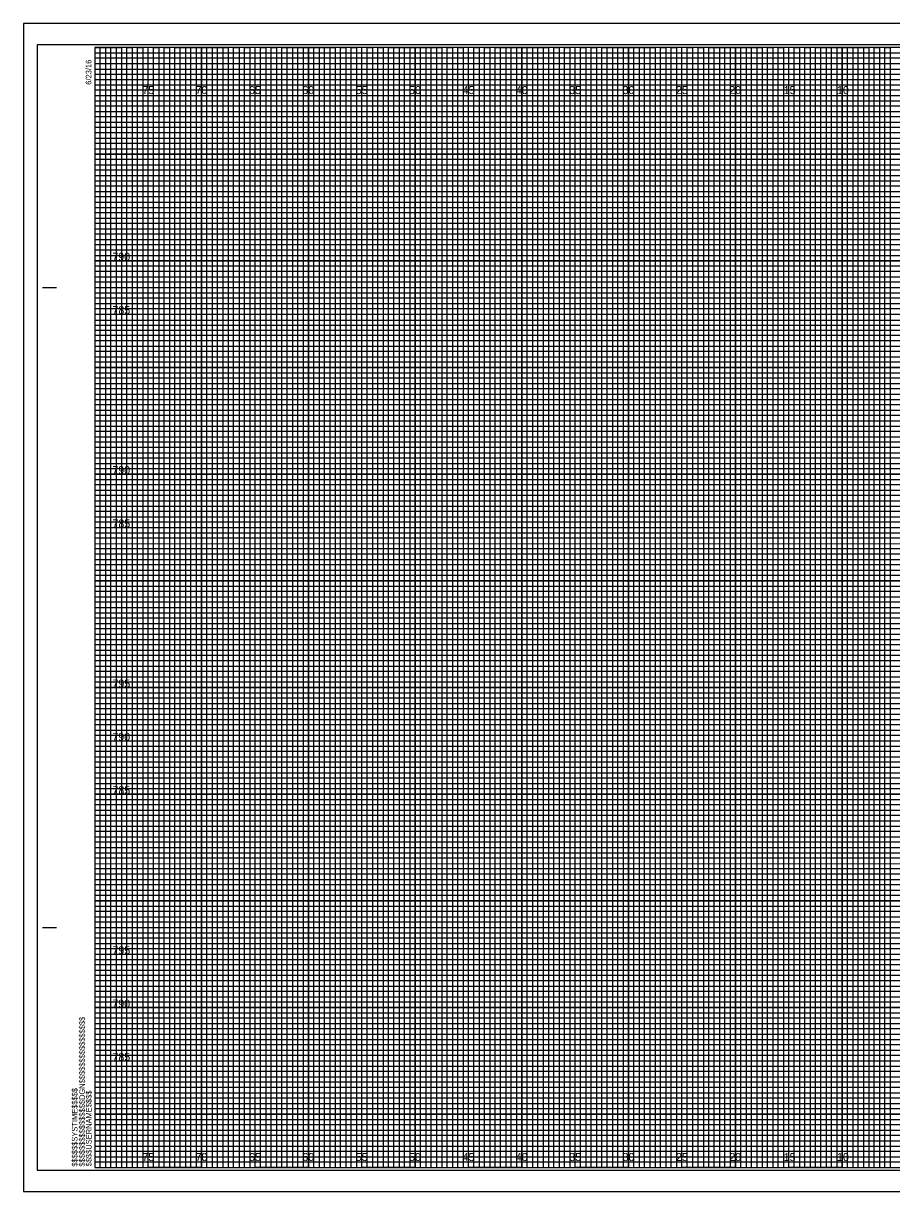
# Model space of a CAD drawing. Extents: x -7 to 162, y 108 to 217.
# Drawn here: x -6.7 to 74.6, y 107.7 to 217.2 of the extents above; entities that cross this region are included whole.
import ezdxf

# ---------------------------------------------------------------- set-up
doc = ezdxf.new("R2010")
doc.units = 0
for name, color, linetype in [('Exist Cross Section Cell', 7, 'Continuous'), ('Exist XS Center Line Elevation Label', 7, 'Continuous'), ('Prop CMT Pvmt Course 2 Wedge', 7, 'Continuous'), ('Prop XS Hydro Elevations', 7, 'Continuous'), ('Prop XS Retaining Wall', 7, 'Continuous'), ('Prop XS SE Text', 7, 'Continuous'), ('Prop XS Side Slope Text', 7, 'Continuous'), ('Sheet Cutting Line CELL', 7, 'Continuous'), ('Sheet DOT Grid CELL', 7, 'Continuous'), ('Sheet Plot Border Inside CELL', 7, 'Continuous'), ('Sheet Plot Border Outside CELL', 7, 'Continuous')]:
    doc.layers.add(name, color=color, linetype=linetype)

msp = doc.modelspace()

# ---------------------------------------------------------------- linework, layer by layer
at = {"layer": 'Exist Cross Section Cell'}
for p, q in [((5, 215), (0, 215)), ((5, 110), (5, 215)), ((15, 215), (10, 215)), ((10, 215), (10, 110)), ((15, 110), (15, 215)), ((25, 215), (20, 215)), ((20, 215), (20, 110)), ((25, 110), (25, 215)), ((35, 215), (30, 215)), ((30, 215), (30, 110)), ((35, 110), (35, 215)), ((45, 215), (40, 215)), ((40, 215), (40, 110)), ((45, 110), (45, 215)), ((55, 215), (50, 215)), ((50, 215), (50, 110)), ((55, 110), (55, 215)), ((65, 215), (60, 215)), ((60, 215), (60, 110)), ((65, 110), (65, 215)), ((75, 215), (70, 215)), ((70, 215), (70, 110)), ((10, 110), (5, 110)), ((20, 110), (15, 110)), ((30, 110), (25, 110)), ((40, 110), (35, 110)), ((50, 110), (45, 110)), ((60, 110), (55, 110)), ((70, 110), (65, 110))]:
    msp.add_line(p, q, dxfattribs=at)
for points in [[(0, 210), (160, 210), (160, 205), (0, 205)], [(0, 200), (160, 200), (160, 195), (0, 195)], [(0, 190), (160, 190), (160, 185), (0, 185)], [(0, 180), (160, 180), (160, 175), (0, 175)], [(0, 170), (160, 170), (160, 165), (0, 165)], [(0, 160), (160, 160), (160, 155), (0, 155)], [(0, 150), (160, 150), (160, 145), (0, 145)], [(0, 140), (160, 140), (160, 135), (0, 135)], [(0, 130), (160, 130), (160, 125), (0, 125)], [(0, 120), (160, 120), (160, 115), (0, 115)]]:
    msp.add_lwpolyline(points, dxfattribs=at)
at = {"layer": 'Exist XS Center Line Elevation Label'}
for points in [[(0, 215), (2.5, 215), (2.5, 110), (7.5, 110), (7.5, 215), (12.5, 215), (12.5, 110), (17.5, 110), (17.5, 215), (22.5, 215), (22.5, 110), (27.5, 110), (27.5, 215), (32.5, 215), (32.5, 110), (37.5, 110), (37.5, 215), (42.5, 215), (42.5, 110), (47.5, 110), (47.5, 215), (52.5, 215), (52.5, 110), (57.5, 110), (57.5, 215), (62.5, 215), (62.5, 110), (67.5, 110), (67.5, 215), (72.5, 215), (72.5, 110), (77.5, 110)], [(0, 212.5), (137.5, 212.5)], [(0, 202.5), (160, 202.5), (160, 207.5), (0, 207.5)], [(0, 192.5), (160, 192.5), (160, 197.5), (0, 197.5)], [(0, 182.5), (160, 182.5), (160, 187.5), (0, 187.5)], [(0, 172.5), (160, 172.5), (160, 177.5), (0, 177.5)], [(0, 162.5), (160, 162.5), (160, 167.5), (0, 167.5)], [(0, 152.5), (160, 152.5), (160, 157.5), (0, 157.5)], [(0, 142.5), (160, 142.5), (160, 147.5), (0, 147.5)], [(0, 132.5), (160, 132.5), (160, 137.5), (0, 137.5)], [(0, 122.5), (160, 122.5), (160, 127.5), (0, 127.5)], [(0, 112.5), (160, 112.5), (160, 117.5), (0, 117.5)]]:
    msp.add_lwpolyline(points, dxfattribs=at)
at = {"layer": 'Prop XS Hydro Elevations'}
for p, q in [((-4.9, 192.5), (-3.65, 192.5)), ((-4.85, 192.5), (-3.6, 192.5)), ((-4.9, 132.5), (-3.65, 132.5)), ((-4.85, 132.5), (-3.6, 132.5)), ((0, 110), (0, 110)), ((0, 110), (0, 110)), ((0, 110), (0, 110)), ((0, 110), (0, 110)), ((0, 110), (0, 110)), ((0, 110), (0, 110)), ((0, 110), (0, 110))]:
    msp.add_line(p, q, dxfattribs=at)
msp.add_lwpolyline([(160, 215), (0, 215), (0, 110), (160, 110)], close=True, dxfattribs=at)
at = {"layer": 'Prop XS Retaining Wall'}
for points in [[(0, 110), (0.5, 110), (0.5, 215), (1, 215), (1, 110)], [(1, 110), (1.5, 110), (1.5, 215), (2, 215), (2, 110)], [(2.5, 110), (3, 110), (3, 215), (3.5, 215), (3.5, 110)], [(3.5, 110), (4, 110), (4, 215), (4.5, 215), (4.5, 110)], [(5, 110), (5.5, 110), (5.5, 215), (6, 215), (6, 110)], [(6, 110), (6.5, 110), (6.5, 215), (7, 215), (7, 110)], [(7.5, 110), (8, 110), (8, 215), (8.5, 215), (8.5, 110)], [(8.5, 110), (9, 110), (9, 215), (9.5, 215), (9.5, 110)], [(10, 110), (10.5, 110), (10.5, 215), (11, 215), (11, 110)], [(11, 110), (11.5, 110), (11.5, 215), (12, 215), (12, 110)], [(12.5, 110), (13, 110), (13, 215), (13.5, 215), (13.5, 110)], [(13.5, 110), (14, 110), (14, 215), (14.5, 215), (14.5, 110)], [(15, 110), (15.5, 110), (15.5, 215), (16, 215), (16, 110)], [(16, 110), (16.5, 110), (16.5, 215), (17, 215), (17, 110)], [(17.5, 110), (18, 110), (18, 215), (18.5, 215), (18.5, 110)], [(18.5, 110), (19, 110), (19, 215), (19.5, 215), (19.5, 110)], [(20, 110), (20.5, 110), (20.5, 215), (21, 215), (21, 110)], [(21, 110), (21.5, 110), (21.5, 215), (22, 215), (22, 110)], [(22.5, 110), (23, 110), (23, 215), (23.5, 215), (23.5, 110)], [(23.5, 110), (24, 110), (24, 215), (24.5, 215), (24.5, 110)], [(25, 110), (25.5, 110), (25.5, 215), (26, 215), (26, 110)], [(26, 110), (26.5, 110), (26.5, 215), (27, 215), (27, 110)], [(27.5, 110), (28, 110), (28, 215), (28.5, 215), (28.5, 110)], [(28.5, 110), (29, 110), (29, 215), (29.5, 215), (29.5, 110)], [(30, 110), (30.5, 110), (30.5, 215), (31, 215), (31, 110)], [(31, 110), (31.5, 110), (31.5, 215), (32, 215), (32, 110)], [(32.5, 110), (33, 110), (33, 215), (33.5, 215), (33.5, 110)], [(33.5, 110), (34, 110), (34, 215), (34.5, 215), (34.5, 110)], [(35, 110), (35.5, 110), (35.5, 215), (36, 215), (36, 110)], [(36, 110), (36.5, 110), (36.5, 215), (37, 215), (37, 110)], [(37.5, 110), (38, 110), (38, 215), (38.5, 215), (38.5, 110)], [(38.5, 110), (39, 110), (39, 215), (39.5, 215), (39.5, 110)], [(40, 110), (40.5, 110), (40.5, 215), (41, 215), (41, 110)], [(41, 110), (41.5, 110), (41.5, 215), (42, 215), (42, 110)], [(42.5, 110), (43, 110), (43, 215), (43.5, 215), (43.5, 110)], [(43.5, 110), (44, 110), (44, 215), (44.5, 215), (44.5, 110)], [(45, 110), (45.5, 110), (45.5, 215), (46, 215), (46, 110)], [(46, 110), (46.5, 110), (46.5, 215), (47, 215), (47, 110)], [(47.5, 110), (48, 110), (48, 215), (48.5, 215), (48.5, 110)], [(48.5, 110), (49, 110), (49, 215), (49.5, 215), (49.5, 110)], [(50, 110), (50.5, 110), (50.5, 215), (51, 215), (51, 110)], [(51, 110), (51.5, 110), (51.5, 215), (52, 215), (52, 110)], [(52.5, 110), (53, 110), (53, 215), (53.5, 215), (53.5, 110)], [(53.5, 110), (54, 110), (54, 215), (54.5, 215), (54.5, 110)], [(55, 110), (55.5, 110), (55.5, 215), (56, 215), (56, 110)], [(56, 110), (56.5, 110), (56.5, 215), (57, 215), (57, 110)], [(57.5, 110), (58, 110), (58, 215), (58.5, 215), (58.5, 110)], [(58.5, 110), (59, 110), (59, 215), (59.5, 215), (59.5, 110)], [(60, 110), (60.5, 110), (60.5, 215), (61, 215), (61, 110)], [(61, 110), (61.5, 110), (61.5, 215), (62, 215), (62, 110)], [(62.5, 110), (63, 110), (63, 215), (63.5, 215), (63.5, 110)], [(63.5, 110), (64, 110), (64, 215), (64.5, 215), (64.5, 110)], [(65, 110), (65.5, 110), (65.5, 215), (66, 215), (66, 110)], [(66, 110), (66.5, 110), (66.5, 215), (67, 215), (67, 110)], [(67.5, 110), (68, 110), (68, 215), (68.5, 215), (68.5, 110)], [(68.5, 110), (69, 110), (69, 215), (69.5, 215), (69.5, 110)], [(70, 110), (70.5, 110), (70.5, 215), (71, 215), (71, 110)], [(71, 110), (71.5, 110), (71.5, 215), (72, 215), (72, 110)], [(72.5, 110), (73, 110), (73, 215), (73.5, 215), (73.5, 110)], [(73.5, 110), (74, 110), (74, 215), (74.5, 215), (74.5, 110)]]:
    msp.add_lwpolyline(points, dxfattribs=at)
at = {"layer": 'Prop XS Side Slope Text'}
for p, q in [((0, 214.5), (130, 214.5)), ((130, 213.99), (0, 213.99)), ((0, 213.99), (0, 213.5)), ((0, 213.5), (130, 213.5)), ((130, 212.94), (0, 212.94)), ((0, 212.94), (0, 212)), ((0, 212), (160, 212))]:
    msp.add_line(p, q, dxfattribs=at)
for points in [[(0, 211.5), (135, 211.5), (160, 211.5), (160, 211), (0, 211)], [(0, 210.5), (160, 210.5), (160, 209.5), (0, 209.5)], [(0, 209), (160, 209), (160, 208.5), (0, 208.49)], [(0, 208), (160, 208), (160, 207), (0, 207)], [(0, 206.5), (160, 206.5), (160, 206), (0, 206)], [(0, 205.5), (160, 205.5), (160, 204.5), (0, 204.5)], [(0, 204), (160, 204), (160, 203.5), (0, 203.5)], [(0, 203), (160, 203), (160, 202), (0, 202)], [(0, 201.5), (160, 201.5), (160, 201), (0, 201)], [(0, 200.5), (160, 200.5), (160, 199.5), (0, 199.5)], [(0, 199), (160, 199), (160, 198.5), (0, 198.5)], [(0, 198), (160, 198), (160, 196.97), (160, 196.5), (160, 196), (0, 196)], [(0, 197), (160, 197), (160, 196.5), (0, 196.5)], [(0, 195.5), (160, 195.5), (160, 194.5), (0, 194.52)], [(0, 194.52), (160, 194.5), (160, 194), (0, 194)], [(0, 193.5), (160, 193.5), (160, 193), (0, 193)], [(0, 192), (160, 192), (160, 191.5), (0, 191.5)], [(0, 191), (160, 191), (160, 190.5), (0, 190.5)], [(-0.04, 189.44), (160, 189.44), (160, 188.94), (-0.04, 188.94)], [(0, 188.5), (160, 188.5), (160, 188), (0, 188)], [(0, 187), (160, 187), (160, 186.5), (0, 186.5)], [(0, 186), (160, 186), (160, 185.5), (0, 185.5)], [(0, 184.5), (160, 184.5), (160, 184), (0, 184)], [(0, 183.5), (160, 183.5), (160, 183), (0, 183)], [(0, 182), (160, 182), (160, 181.5), (0, 181.5)], [(0, 181), (160, 181), (160, 180.5), (0, 180.5)], [(0, 179.5), (160, 179.5), (160, 178.99), (0, 179)], [(0, 178.5), (160, 178.5), (160, 178), (0, 178)], [(0, 177), (160, 177), (160, 176.5), (0, 176.5)], [(0, 176), (160, 176), (160, 175.5), (0, 175.5)], [(0, 174.5), (160, 174.5), (160, 174), (0, 174)], [(0, 173.5), (160, 173.5), (160, 173), (0, 173)], [(0, 172), (160, 172), (160, 171.5), (0, 171.5)], [(0, 171), (160, 171), (160, 170.5), (0, 170.5)], [(0, 169.5), (160, 169.5), (160, 169), (0, 169)], [(0, 168.5), (160.03, 168.46), (160, 168), (0, 168)], [(0, 167), (160, 167), (160, 166.5), (0, 166.5)], [(0, 166), (160, 166), (160, 165.5), (0, 165.5)], [(0, 164.5), (160, 164.5), (160, 164), (0, 164)], [(0, 163.5), (160, 163.5), (160, 163), (0, 163)], [(0, 162), (160, 162), (160, 161.5), (0, 161.5)], [(0, 161), (160, 161), (160, 160.5), (0, 160.5)], [(0, 159.5), (160, 159.5), (160, 159), (0, 159)], [(0, 158.5), (160, 158.5), (160, 158), (0, 158)], [(0, 157), (160, 157), (160, 156.5), (0, 156.5)], [(0, 156), (160, 156), (160, 155.5), (0, 155.5)], [(0, 154.5), (160, 154.5), (160, 154), (0, 154)], [(0, 153.5), (160, 153.5), (160, 153), (0, 153)], [(0, 152), (160, 152), (160, 151.5), (0, 151.5)], [(0, 151), (160, 151), (160, 150.5), (0, 150.5)], [(0, 149.5), (160, 149.5), (160, 148.99), (0, 149)], [(0, 148.5), (160, 148.5), (160, 148), (0, 148)], [(0, 147), (160, 147), (160, 146.5), (0, 146.5)], [(0, 146), (160, 146), (160, 145.5), (0, 145.5)], [(0, 144.5), (160, 144.5), (160, 144), (0, 144)], [(0, 143.5), (160, 143.5), (160, 143), (0, 143)], [(0, 142), (160, 142), (160, 141.5), (0, 141.5)], [(0, 141), (160, 141), (160, 140.5), (0, 140.5)], [(0, 139.5), (160, 139.5), (160, 139), (0, 139)], [(0, 138.5), (160.03, 138.46), (160, 138), (0, 138)], [(0, 137), (160, 137), (160, 136.5), (0, 136.5)], [(0, 136), (160, 136), (160, 135.5), (0, 135.5)], [(0, 134.5), (160, 134.5), (160, 134), (0, 134)], [(0, 133.5), (160, 133.5), (160, 133), (0, 133)], [(0, 132), (160, 132), (160, 131.5), (0, 131.5)], [(0, 131), (160, 131), (160, 130.5), (0, 130.5)], [(0, 129.5), (160, 129.5), (160, 129), (0, 129)], [(0, 128.5), (160, 128.5), (160, 128), (0, 128)], [(0, 127), (160, 127), (160, 126.5), (0, 126.5)], [(0, 126), (160, 126), (160, 125.5), (0, 125.5)], [(0, 124.5), (160, 124.5), (160, 124), (0, 124)], [(0, 123.5), (160, 123.5), (160, 123), (0, 123)], [(0, 122), (160, 122), (160, 121.5), (0, 121.5)], [(0, 121), (160, 121), (160, 120.5), (0, 120.5)], [(0, 119.5), (160, 119.5), (160, 119), (0, 119)], [(0, 118.5), (160, 118.5), (160, 118), (0, 118)], [(0, 117), (160, 117), (160, 116.5), (0, 116.5)], [(0, 116), (160, 116), (160, 115.5), (0, 115.5)], [(0, 114.5), (160, 114.5), (160, 114), (0, 114)], [(0, 113.5), (160, 113.5), (160, 113), (0, 113)], [(0, 112), (160, 112), (160, 111.5), (0, 111.5)], [(0, 111), (160, 111), (160, 110.5), (0, 110.5)]]:
    msp.add_lwpolyline(points, dxfattribs=at)
at = {"layer": 'Sheet Cutting Line CELL'}
for p, q in [((161.65, 217.25), (-6.7, 217.25)), ((-6.7, 217.25), (-6.7, 107.75)), ((-6.7, 107.75), (161.65, 107.75))]:
    msp.add_line(p, q, dxfattribs=at)
at = {"layer": 'Sheet DOT Grid CELL'}
for p, q in [((5, 110), (5, 215)), ((10, 110), (10, 215)), ((15, 110), (15, 215)), ((20, 110), (20, 215)), ((25, 110), (25, 215)), ((30, 110), (30, 215)), ((35, 110), (35, 215)), ((40, 110), (40, 215)), ((45, 110), (45, 215)), ((50, 110), (50, 215)), ((55, 110), (55, 215)), ((60, 110), (60, 215)), ((65, 110), (65, 215)), ((70, 110), (70, 215)), ((0, 210), (160, 210)), ((0, 205), (160, 205)), ((0, 200), (160, 200)), ((0, 195), (160, 195)), ((0, 190), (160, 190)), ((0, 185), (160, 185)), ((0, 180), (160, 180)), ((0, 175), (160, 175)), ((0, 170), (160, 170)), ((0, 165), (160, 165)), ((0, 160), (160, 160)), ((0, 155), (160, 155)), ((0, 150), (160, 150)), ((0, 145), (160, 145)), ((0, 140), (160, 140)), ((0, 135), (160, 135)), ((0, 130), (160, 130)), ((0, 125), (160, 125)), ((0, 120), (160, 120)), ((0, 115), (160, 115))]:
    msp.add_line(p, q, dxfattribs=at)
at = {"layer": 'Sheet Plot Border Inside CELL'}
msp.add_lwpolyline([(-5.4, 109.75), (161.2, 109.75), (161.2, 215.25), (-5.4, 215.25)], close=True, dxfattribs=at)
at = {"layer": 'Sheet Plot Border Outside CELL'}
msp.add_lwpolyline([(-6.7, 107.75), (161.65, 107.75), (161.65, 217.25), (-6.7, 217.25)], close=True, dxfattribs=at)

# ---------------------------------------------------------------- texts
at = {"layer": 'Prop CMT Pvmt Course 2 Wedge'}
for s, p in [('790', (1.63, 195)), ('785', (1.64, 190)), ('790', (1.63, 175)), ('785', (1.64, 170)), ('795', (1.64, 155)), ('790', (1.63, 150)), ('785', (1.64, 145)), ('795', (1.64, 130)), ('790', (1.63, 125)), ('785', (1.64, 120))]:
    msp.add_text(s, height=0.75, dxfattribs=at).set_placement(p)
at = {"layer": 'Prop XS Hydro Elevations'}
for s, p in [('6/23/16', (-0.33, 211.5)), ('$$$$$$$$$$$$$$$$DGN$$$$$$$$$$$$$$$$', (-0.94, 110.09)), ('$$$$$$SYSTIME$$$$$', (-1.63, 110.09)), ('$$$$USERNAME$$$$', (-0.31, 110.12))]:
    msp.add_text(s, height=0.525, rotation=90, dxfattribs=at).set_placement(p)
at = {"layer": 'Prop XS SE Text'}
for s, p in [('75', (4.44, 210.62)), ('70', (9.43, 210.62)), ('65', (14.44, 210.62)), ('60', (19.43, 210.62)), ('55', (24.44, 210.62)), ('50', (29.43, 210.62)), ('45', (34.44, 210.62)), ('40', (39.43, 210.62)), ('35', (44.44, 210.62)), ('30', (49.43, 210.62)), ('25', (54.44, 210.62)), ('20', (59.43, 210.62)), ('15', (64.53, 210.62)), ('10', (69.52, 210.62)), ('75', (4.44, 110.62)), ('70', (9.43, 110.62)), ('65', (14.44, 110.62)), ('60', (19.43, 110.62)), ('55', (24.44, 110.62)), ('50', (29.43, 110.62)), ('45', (34.44, 110.62)), ('40', (39.43, 110.62)), ('35', (44.44, 110.62)), ('30', (49.43, 110.62)), ('25', (54.44, 110.62)), ('20', (59.43, 110.62)), ('15', (64.53, 110.62)), ('10', (69.52, 110.62))]:
    msp.add_text(s, height=0.75, dxfattribs=at).set_placement(p)

doc.saveas('drawing.dxf')
